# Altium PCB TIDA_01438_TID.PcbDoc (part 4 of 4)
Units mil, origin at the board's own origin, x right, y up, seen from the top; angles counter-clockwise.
Board outline 6250 x 2150 mil, 4 copper layers (Top Layer, V-, V+, Bottom Layer), stack 61.6 mil thick; 360 components, 217 nets, 1141 pads, 401 vias.
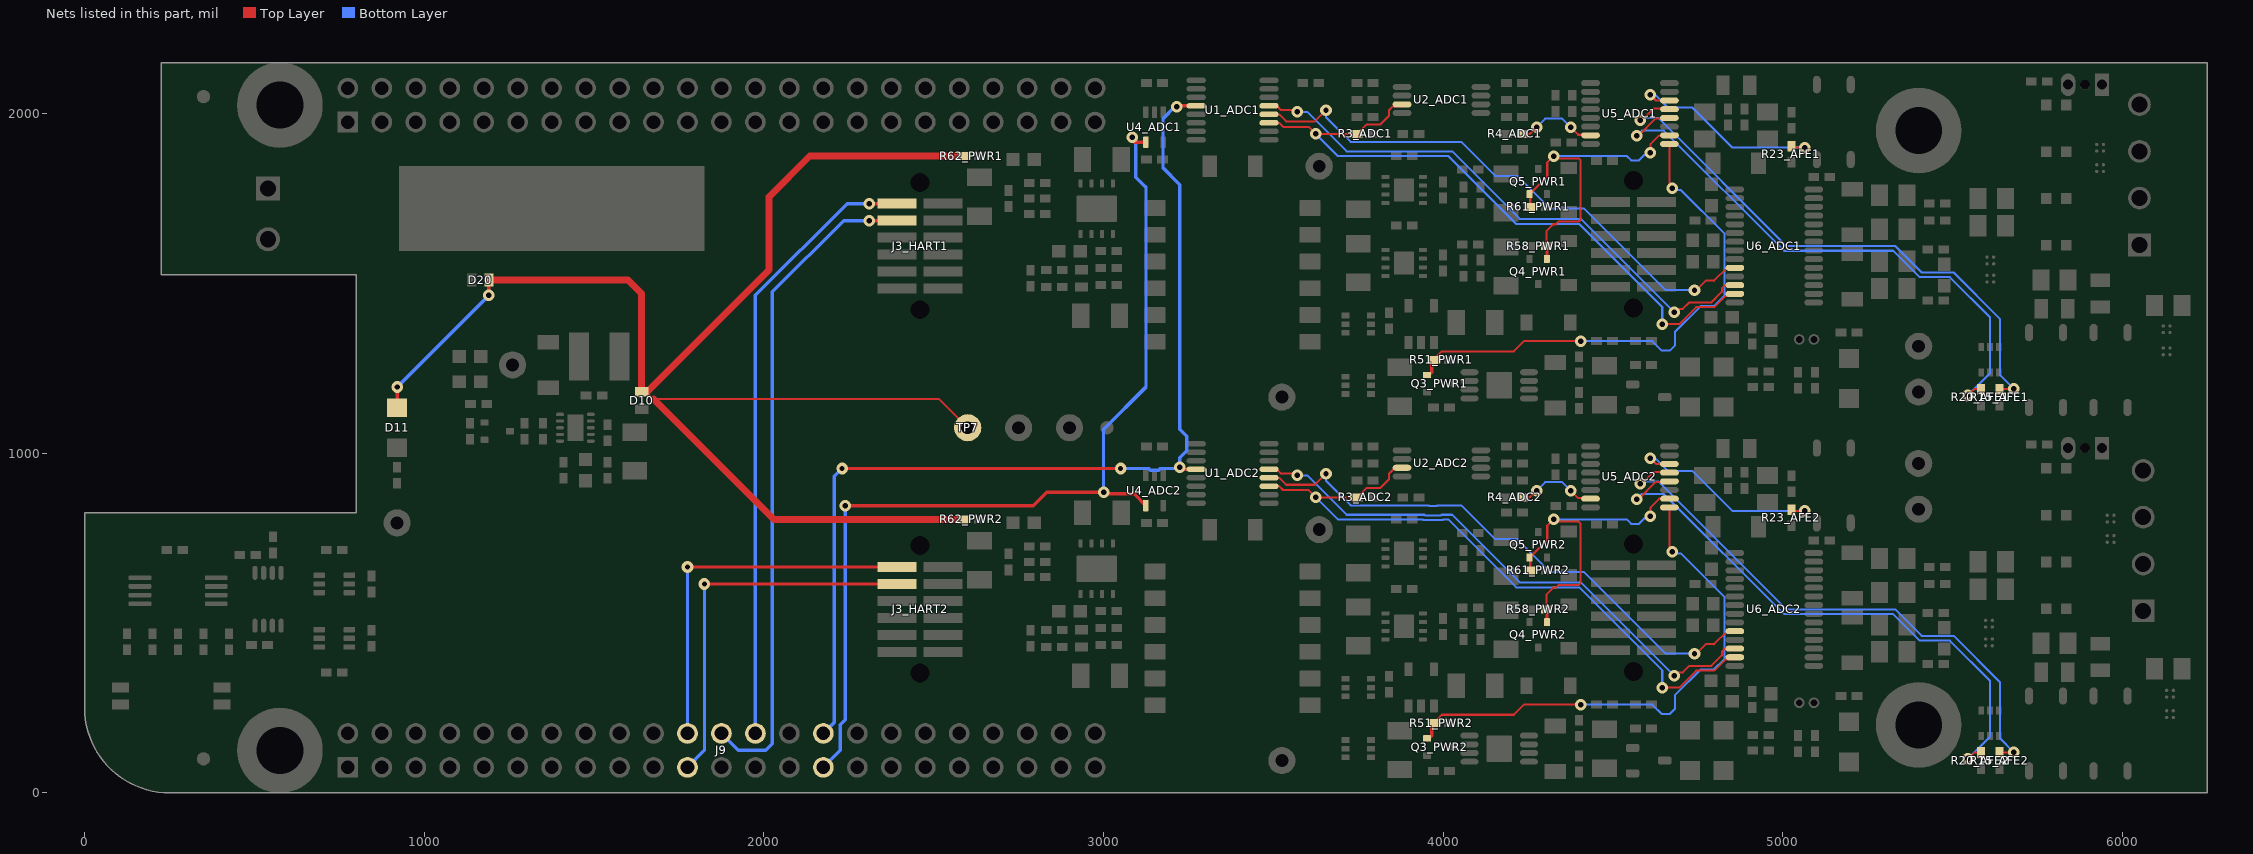
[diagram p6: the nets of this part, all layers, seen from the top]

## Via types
v1: diameter 34, hole 16, Top Layer to Bottom Layer, 337 vias
v2: diameter 19.68, hole 7.87, Top Layer to Bottom Layer, 36 vias
v3: diameter 39.37, hole 19.68, Top Layer to Bottom Layer, 24 vias
v4: diameter 30, hole 10, Top Layer to Bottom Layer, 4 vias

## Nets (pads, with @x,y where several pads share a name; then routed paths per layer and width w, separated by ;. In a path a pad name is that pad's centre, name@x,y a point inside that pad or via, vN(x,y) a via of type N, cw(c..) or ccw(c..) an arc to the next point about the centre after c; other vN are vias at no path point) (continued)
SPI_ISO_CS_ADC1: U1_ADC1.12 U6_ADC1.10 | length 1663.9
  Top Layer w6: v1@3650,2010 v1@3655,2015 ; v1(3655,2010) 3622.13,1977.13 3537.87,1977.13 3518.31,1996.69 U1_ADC1.12@3488.41,1996.69 ; v1(4740,1480) 4745.58,1480 4773.45,1507.87 4796.55,1507.87 4797.11,1507.31 4835.82,1546.02 U6_ADC1.10@4858.86,1546.02 U6_ADC1.10@4858.86,1544.76 ; U1_ADC1.12@3488.41,1996.69 3487.28,1996.69 U1_ADC1.12@3487.28,1997.82 U1_ADC1.12@3488.41,1996.69
  Bottom Layer w6: v1(3655,2010) 3655,1989.24 3727.62,1916.62 4053,1916.62 4152.87,1816.75 4218.62,1816.75 4315.37,1720 4415,1720 4655,1480 v1(4740,1480)
SPI_ISO_CS_ADC2: U1_ADC2.12 U6_ADC2.10 | length 1661.5
  Top Layer w6: U1_ADC2.12@3488.41,926.69 3518.31,926.69 3537.87,907.13 3622.13,907.13 v1(3655,940) ; v1@3650,940 v1@3655,945 ; v1(4740,410) 4745.58,410 4773.45,437.87 4796.55,437.87 4797.11,437.31 4835.82,476.02 U6_ADC2.10@4858.86,476.02 U6_ADC2.10@4858.86,474.76
  Bottom Layer w6: v1(3655,940) 3655,919.24 3727.62,846.62 3956.7,846.62 3958.45,844.87 3981.55,844.87 3983.3,846.62 4053,846.62 4152.87,746.75 4218.62,746.75 4315.37,650 4415,650 4655,410 v1(4740,410)
SPI_ISO_MISO_ADC1: R3_ADC1.2 U1_ADC1.11 U2_ADC1.7 U6_ADC1.13 | length 2007.5
  Top Layer w6: U1_ADC1.11@3487.28,1972.82 3517.19,1972.82 3528.31,1961.69 3528.69,1961.69 3529.25,1961.13 3603.87,1961.13 v1(3625,1940) R3_ADC1.2@3746.38,1940 3773.69,1967.32 3813.87,1967.32 3840.43,1993.87 3840.43,2009.79 3851.98,2021.35 3873,2021.35 U2_ADC1.7@3878.86,2027.2 ; v1(4645,1380) 4695,1380 4745,1430 4798.59,1430 4831.98,1463.39 4853,1463.39 U6_ADC1.13@4858.86,1469.25 U6_ADC1.13@4834.25,1469.25
  Bottom Layer w6: v1(3625,1940) 3690,1875 4015,1875 4215,1675 4400.38,1675 4645,1430.38 v1(4645,1380)
SPI_ISO_MISO_ADC2: R3_ADC2.2 U1_ADC2.11 U2_ADC2.7 U6_ADC2.13 | length 2008
  Top Layer w6: U1_ADC2.11@3487.28,902.82 3517.19,902.82 3528.31,891.69 3528.69,891.69 3529.25,891.13 3603.87,891.13 v1(3625,870) R3_ADC2.2@3746.38,870 3773.69,897.32 3813.87,897.32 3840.43,923.87 3840.43,939.79 3855.59,954.95 U2_ADC2.7@3878.86,954.95 ; v1(4645,310) 4695,310 4745,360 4798.59,360 4831.98,393.39 4853,393.39 U6_ADC2.13@4858.86,399.25 U6_ADC2.13@4834.25,399.25
  Bottom Layer w6: v1(3625,870) 3690,805 3939.46,805 3941.21,803.25 3998.79,803.25 4000.54,805 4015,805 4215,605 4400.38,605 4645,360.38 v1(4645,310)
SPI_ISO_MOSI_ADC1: U1_ADC1.13 U6_ADC1.12 | length 1670.9
  Top Layer w6: U1_ADC1.13@3487.28,2022.82 3509.47,2022.82 3521.71,2010.57 3559.43,2010.57 3565,2005 v1(3570,2005) ; v1(4680,1415) 4685,1415 4695,1425 4705.96,1425 4724.83,1443.87 4789.25,1443.87 4820.43,1475.05 4820.43,1485.43 4830,1495 4830.16,1494.84 U6_ADC1.12@4858.86,1494.84 U6_ADC1.12@4853,1488.98
  Bottom Layer w6: v1(3570,2005) 3600,2005 3716.13,1888.87 4026.13,1888.87 4225,1690 4405,1690 v1(4680,1415)
SPI_ISO_MOSI_ADC2: U1_ADC2.13 U6_ADC2.12 | length 1672.4
  Top Layer w6: U1_ADC2.13@3487.28,952.82 3509.47,952.82 3521.71,940.57 3559.43,940.57 3565,935 v1(3570,935) ; v1(4680,345) 4685,345 4695,355 4705.96,355 4724.83,373.87 4789.25,373.87 4820.43,405.05 4820.43,415.43 4830,425 4830.16,424.84 U6_ADC2.12@4858.86,424.84 U6_ADC2.12@4853,418.98
  Bottom Layer w6: v1(3570,935) 3600,935 3716.13,818.87 3945.21,818.87 3946.96,817.12 3993.04,817.12 3994.79,818.87 4026.13,818.87 4225,620 4405,620 v1(4680,345)
SPI_MISO: J9.29 U4_ADC1.4 U4_ADC2.4 | length 2893.9
  Top Layer w10: v1@2225.71,845.71 2793.36,845.71 2832.65,885 v1(3000,885) 3004.87,880.13 3089.99,880.13 U4_ADC2.4@3124.41,845.71 ; v1(3085,1930) 3085,1921.42 3090.71,1915.71 U4_ADC1.4@3124.41,1915.71
  Bottom Layer w10: J9.29@2175,75 2225,125 2225,200 2240,215 v1(2240,845.71) ; v1(3000,885) 3000,1070 3125,1195 3125,1785 3122.75,1785 3095.13,1812.63 3095.13,1919.87 v1(3085,1930)
SPI_MOSI: J9.30 U1_ADC1.4 U1_ADC2.4 | length 3038.3
  Top Layer w10: v1(2230,955) v1(3050,955) ; v1(3215,2020) 3210,2020 3212.82,2022.82 U1_ADC1.4@3272.72,2022.82 ; v1(3224.14,959.14) 3224.14,955.86 3227.18,952.82 U1_ADC2.4@3272.72,952.82
  Bottom Layer w10: J9.30@2175,175 2207.13,207.13 2207.13,932.13 v1(2230,955) ; v1(3050,955) 3132.75,955 3137.63,950.13 3162.37,950.13 3167.25,955 3215,955 3220,960 3220.86,959.14 v1(3224.14,959.14) 3224.14,986.89 3244.87,1007.63 3244.87,1049.87 3224.14,1070.61 3224.14,1790.86 3175,1840 3175,1985 v1@3210,2020
SW_4_20MA_ADC1: Q3_PWR1.1 R51_PWR1.2 U5_ADC1.1 | length 1557
  Top Layer w6: R51_PWR1.2@3971.38,1275 3996.38,1300 4207.75,1300 4237.75,1330 v1(4405,1330) ; U5_ADC1.1@4666.14,1910.43 4666.14,1788.86 v1(4675,1780)
  Top Layer w10: Q3_PWR1.1@3958.5,1230.59 3966.38,1238.46 R51_PWR1.2@3966.38,1275
  Bottom Layer w6: v1(4405,1330) 4615.58,1330 4643.45,1302.13 4666.55,1302.13 4682.87,1318.45 4682.87,1358.25 4757.87,1433.25 4797.29,1433.25 4827.87,1463.83 4827.87,1647.13 4700,1775 4675,1775 v1(4675,1780)
SW_4_20MA_ADC2: Q3_PWR2.1 R51_PWR2.2 U5_ADC2.1 | length 1557
  Top Layer w6: R51_PWR2.2@3971.38,205 3996.38,230 4207.75,230 4237.75,260 v1(4405,260) ; U5_ADC2.1@4666.14,840.43 4666.14,718.86 v1(4675,710)
  Top Layer w10: Q3_PWR2.1@3958.5,160.59 3966.38,168.46 R51_PWR2.2@3966.38,205
  Bottom Layer w6: v1(4405,260) 4615.58,260 4643.45,232.13 4666.55,232.13 4682.87,248.45 4682.87,288.25 4757.87,363.25 4797.29,363.25 4827.87,393.83 4827.87,577.13 4700,705 4675,705 v1(4675,710)
SW_ASUPPLY_PWR1: Q4_PWR1.1 Q5_PWR1.1 R58_PWR1.1 R61_PWR1.1 U5_ADC1.2 | length 1032.2
  Top Layer w6: R61_PWR1.1@4256.38,1725 4256.38,1766.54 4254.41,1768.5 4259.95,1768.5 4306.44,1815 4306.44,1856.44 4318.35,1868.35 4398.52,1868.35 4404.89,1861.98 4404.89,1688.02 4398.52,1681.65 4339.2,1681.65 4331.68,1674.13 4324.13,1674.13 4303.62,1653.62 R58_PWR1.1@4303.62,1610 ; v1(4610,1885) 4610,1910 4636.02,1936.02 U5_ADC1.2@4666.14,1936.02
  Top Layer w10: R58_PWR1.1@4303.62,1610 4305.59,1608.03 Q4_PWR1.1@4305.59,1566.5
  Bottom Layer w6: v1(4325,1875) 4540.58,1875 4553.45,1862.13 4576.55,1862.13 4592.73,1878.32 4603.32,1878.32 v1(4610,1885)
SW_ASUPPLY_PWR2: Q4_PWR2.1 Q5_PWR2.1 R58_PWR2.1 R61_PWR2.1 U5_ADC2.2 | length 1032.2
  Top Layer w6: R61_PWR2.1@4256.38,655 4256.38,696.54 4254.41,698.5 4259.95,698.5 4306.44,745 4306.44,786.44 4318.35,798.35 4398.52,798.35 4404.89,791.98 4404.89,618.02 4398.52,611.65 4339.2,611.65 4331.68,604.13 4324.13,604.13 4303.62,583.62 R58_PWR2.1@4303.62,540 ; v1(4610,815) 4610,840 4636.02,866.02 U5_ADC2.2@4666.14,866.02
  Top Layer w10: R58_PWR2.1@4303.62,540 4305.59,538.03 Q4_PWR2.1@4305.59,496.5
  Bottom Layer w6: v1(4325,805) 4540.58,805 4553.45,792.13 4576.55,792.13 4592.73,808.32 4603.32,808.32 v1(4610,815)
SW_BURDEN_ADC1: R23_AFE1.1 U5_ADC1.6 | length 623.7
  Top Layer w6: v1(4610,2055) 4626.61,2038.39 U5_ADC1.6@4666.14,2038.39 ; R23_AFE1.1@5025,1903.62 5028.62,1900 v1(5065,1900)
  Bottom Layer w6: v1(4610,2055) 4624.62,2055 4661.75,2017.87 4733.35,2017.87 4851.22,1900 5060,1900 v1(5065,1900)
SW_BURDEN_ADC2: R23_AFE2.1 U5_ADC2.6 | length 623.7
  Top Layer w6: v1(4610,985) 4626.61,968.39 U5_ADC2.6@4666.14,968.39 ; R23_AFE2.1@5025,833.62 5028.62,830 v1(5065,830)
  Bottom Layer w6: v1(4610,985) 4624.62,985 4661.75,947.87 4733.35,947.87 4851.22,830 5060,830 v1(5065,830)
SW_HV_ADC1: R20_AFE1.1 U5_ADC1.4 | length 1693.5
  Top Layer w6: v1(4570,1935) 4575,1935 4625,1985 4661.63,1985 U5_ADC1.4@4660.28,1986.35 ; v1(5545,1170) 5563.62,1188.62 R20_AFE1.1@5583.35,1188.62
  Bottom Layer w6: v1@4572.21,1935 v1(4570,1935) 4585,1950 4650,1950 5003.87,1596.13 5324.83,1596.13 5402.71,1518.25 5491.75,1518.25 5610,1400 5610,1235 v1(5545,1170)
SW_HV_ADC2: R20_AFE2.1 U5_ADC2.4 | length 1693.5
  Top Layer w6: v1(4570,865) 4575,865 4625,915 4661.63,915 U5_ADC2.4@4660.28,916.35 ; v1(5545,100) 5563.62,118.62 R20_AFE2.1@5583.35,118.62
  Bottom Layer w6: v1@4572.21,865 v1(4570,865) 4585,880 4650,880 5003.87,526.13 5324.83,526.13 5402.71,448.25 5491.75,448.25 5610,330 5610,165 v1(5545,100)
SW_RTD_LOOP_ADC1: R15_AFE1.1 U5_ADC1.5 | length 1685.5
  Top Layer w6: v1(4580,1980) 4580,1985 4585,1980 4620,2015 4663.35,2015 U5_ADC1.5@4666.14,2017.8 ; R15_AFE1.1@5638.35,1188.62 5678.62,1188.62 v1(5680,1190)
  Bottom Layer w6: v1@4590,1980 4582.75,1987.25 4632.75,1987.25 5010,1610 5330.58,1610 5408.45,1532.13 5502.87,1532.13 5640,1395 5640,1230 v1(5680,1190)
SW_RTD_LOOP_ADC2: R15_AFE2.1 U5_ADC2.5 | length 1685.5
  Top Layer w6: v1(4580,910) 4580,915 4585,910 4620,945 4663.35,945 U5_ADC2.5@4666.14,947.8 ; R15_AFE2.1@5638.35,118.62 5678.62,118.62 v1(5680,120)
  Bottom Layer w6: v1@4590,910 4582.75,917.25 4632.75,917.25 5010,540 5330.58,540 5408.45,462.13 5502.87,462.13 5640,325 5640,160 v1(5680,120)
SW_TEMP_ADC1: R4_ADC1.2 U5_ADC1.15 | length 240.1
  Top Layer w6: R4_ADC1.2@4233.62,1940 4255,1940 v1(4275,1960) ; v1(4375,1960) 4397.31,1937.68 4433.86,1937.68 U5_ADC1.15@4433.86,1936.02
  Bottom Layer w6: v1(4275,1960) 4300,1985 4350,1985 v1(4375,1960)
SW_TEMP_ADC2: R4_ADC2.2 U5_ADC2.15 | length 240.1
  Top Layer w6: R4_ADC2.2@4233.62,870 4255,870 v1(4275,890) ; v1(4375,890) 4397.31,867.68 4433.86,867.68 U5_ADC2.15@4433.86,866.02
  Bottom Layer w6: v1(4275,890) 4300,915 4350,915 v1(4375,890)
UART_RXD1: J3_HART1.1 J9.26 | length 1819.3
  Top Layer w10: v1(2310,1735) J3_HART1.1@2392.48,1735
  Bottom Layer w10: J9.26@1975,175 1975,1465 2245,1735 v1(2310,1735)
UART_RXD2: J3_HART2.1 J9.22 | length 1107.5
  Top Layer w10: v1(1775,665) J3_HART2.1@2392.48,665
  Bottom Layer w10: J9.22@1775,175 v1(1775,665)
UART_TXD1: J3_HART1.3 J9.24 | length 1963.5
  Top Layer w10: v1(2310,1685) J3_HART1.3@2392.48,1685
  Bottom Layer w10: J9.24@1875,175 1925,125 2005,125 2025,145 2025,1475 2235,1685 v1(2310,1685)
UART_TXD2: J3_HART2.3 J9.21 | length 1128.2
  Top Layer w10: v1(1825,615) J3_HART2.3@2392.48,615
  Bottom Layer w10: J9.21@1775,75 1825,125 v1(1825,615)
VIN: D10.1 D11.2 D20.1 R62_PWR1.1 R62_PWR2.1 TP7.1 | length 4654.6
  Top Layer w6: D10.1@1654.13,1180.59 1674.72,1160 2515,1160 TP7.1@2600,1075
  Top Layer w10: D11.2@920,1134.06 v1(920,1195) ; v1(1190,1465) 1190,1509.41 D20.1@1190.59,1510
  Top Layer w20: D20.1@1190.59,1510 1600,1510 1640,1470 D10.1@1640,1180.59 1654.13,1180.59 1655.59,1180.59 2015,1540 2015,1755 2135,1875 R62_PWR1.1@2586.38,1875 ; 1674.72,1160 2029.72,805 R62_PWR2.1@2586.38,805
  Bottom Layer w10: v1(920,1195) 1185,1460 1190,1460 v1(1190,1465)
pads on no net: D4_AFE1.2 D4_AFE1.5 D4_AFE2.2 D4_AFE2.5 D13_PWR1.2 D13_PWR1.5 D13_PWR2.2 D13_PWR2.5 D16_PWR1.2 D16_PWR1.5 D16_PWR2.2 D16_PWR2.5 FID1.1 FID2.1 FID3.1 J3_HART1.2 J3_HART1.4 J3_HART1.6 J3_HART1.8 J3_HART1.10 J3_HART1.12 J3_HART1.MH1 J3_HART1.MH2 J3_HART2.2 J3_HART2.4 J3_HART2.6 J3_HART2.8 J3_HART2.10 J3_HART2.12 J3_HART2.MH1 J3_HART2.MH2 J4_HART1.2 J4_HART1.5 J4_HART1.6 J4_HART1.10 J4_HART1.11 J4_HART1.12 J4_HART1.MH1 J4_HART1.MH2 J4_HART2.2 J4_HART2.5 J4_HART2.6 J4_HART2.10 J4_HART2.11 J4_HART2.12 J4_HART2.MH1 J4_HART2.MH2 J8.3 J8.4 J8.5 J8.6 J8.7 J8.8 J8.9 J8.10 J8.13 J8.14 J8.15 J8.16 J8.17 J8.18 J8.19 J8.20 J8.21 J8.22 J8.23 J8.24 J8.25 J8.26 J8.27 J8.28 J8.29 J8.30 J8.31 J8.32 J8.33 J8.34 J8.35 J8.36 J8.37 J8.38 J8.39 J8.40 J8.41 J8.42 J8.43 J8.44 J8.45 J8.46 J9.9 J9.10 J9.11 J9.12 J9.13 J9.14 J9.15 J9.16 J9.17 J9.18 J9.23 J9.32 J9.33 J9.34 J9.35 J9.36 J9.37 J9.38 J9.39 J9.40 J9.41 Logo1.0 MH1.1 MH2.1 MH3.1 MH4.1 T1_PWR1.1 T1_PWR1.3 T1_PWR1.5 T1_PWR1.6 T1_PWR2.1 T1_PWR2.3 T1_PWR2.5 T1_PWR2.6 U3_ADC1.MH U3_ADC2.MH U5_ADC1.9 U5_ADC2.9 U6_ADC1.14 U6_ADC2.14 U12_PWR1.3 U12_PWR1.6 U12_PWR1.7 U12_PWR2.3 U12_PWR2.6 U12_PWR2.7 U13_PWR1.4 U13_PWR1.5 U13_PWR2.4 U13_PWR2.5 U14_PWR1.3 U14_PWR1.7 U14_PWR2.3 U14_PWR2.7 U16_PWR1.3 U16_PWR1.7 U16_PWR2.3 U16_PWR2.7
copper on no net: | length 104231.7
  Top Layer w1: 9194.12,4730.32 9293.8,4830 9413.8,4950 9533.8,5070 9653.8,5190 9773.8,5310 9893.8,5430 10013.8,5550 10133.8,5670 10253.8,5790 10313.8,5850 ; 9194.12,4790.32 9233.8,4830 9353.8,4950 9473.8,5070 9593.8,5190 9713.8,5310 9833.8,5430 9953.8,5550 10073.8,5670 10193.8,5790 10313.8,5910 ; 9194.12,4850.32 9293.8,4950 9413.8,5070 9533.8,5190 9653.8,5310 9773.8,5430 9893.8,5550 10013.8,5670 10133.8,5790 10253.8,5910 10313.8,5970 ; 9194.12,4910.32 9233.8,4950 9353.8,5070 9473.8,5190 9593.8,5310 9713.8,5430 9833.8,5550 9953.8,5670 10073.8,5790 10193.8,5910 10313.8,6030 ; 9194.12,4970.32 9293.8,5070 9413.8,5190 9533.8,5310 9653.8,5430 9773.8,5550 9893.8,5670 10013.8,5790 10133.8,5910 10253.8,6030 ; 9194.12,5030.32 9233.8,5070 9353.8,5190 9473.8,5310 9593.8,5430 9713.8,5550 9833.8,5670 9953.8,5790 10073.8,5910 10193.8,6030 ; 9194.12,5090.32 9293.8,5190 9413.8,5310 9533.8,5430 9653.8,5550 9773.8,5670 9893.8,5790 10013.8,5910 10133.8,6030 ; 9194.12,5150.32 9233.8,5190 9353.8,5310 9473.8,5430 9593.8,5550 9713.8,5670 9833.8,5790 9953.8,5910 10073.8,6030 ; 9194.12,5210.32 9293.8,5310 9413.8,5430 9533.8,5550 9653.8,5670 9773.8,5790 9893.8,5910 10013.8,6030 ; 9194.12,5270.32 9233.8,5310 9353.8,5430 9473.8,5550 9593.8,5670 9713.8,5790 9833.8,5910 9953.8,6030 ; 9194.12,5330.32 9293.8,5430 9413.8,5550 9533.8,5670 9653.8,5790 9773.8,5910 9893.8,6030 ; 9194.12,5390.32 9233.8,5430 9353.8,5550 9473.8,5670 9593.8,5790 9713.8,5910 9833.8,6030 ; 9194.12,5450.32 9293.8,5550 9413.8,5670 9533.8,5790 9653.8,5910 9773.8,6030 ; 9194.12,5510.32 9233.8,5550 9353.8,5670 9473.8,5790 9593.8,5910 9713.8,6030 ; 9194.12,5570.32 9293.8,5670 9413.8,5790 9533.8,5910 9653.8,6030 ; 9194.12,5630.32 9233.8,5670 9353.8,5790 9473.8,5910 9593.8,6030 ; 9194.12,5690.32 9293.8,5790 9413.8,5910 9533.8,6030 ; 9194.12,5750.32 9233.8,5790 9353.8,5910 9473.8,6030 ; 9194.12,5810.32 9293.8,5910 9413.8,6030 ; 9194.12,5870.32 9233.8,5910 9353.8,6030 ; 9194.12,5930.32 9293.8,6030 ; 9194.12,5990.32 9233.8,6030 ; 9233.8,4710 9353.8,4830 9473.8,4950 9593.8,5070 9713.8,5190 9833.8,5310 9953.8,5430 10073.8,5550 10193.8,5670 10313.8,5790 ; 9293.8,4710 9413.8,4830 9533.8,4950 9653.8,5070 9773.8,5190 9893.8,5310 10013.8,5430 10133.8,5550 10253.8,5670 10313.8,5730 ; 9353.8,4710 9473.8,4830 9593.8,4950 9713.8,5070 9833.8,5190 9953.8,5310 10073.8,5430 10193.8,5550 10313.8,5670 ; 9413.8,4710 9533.8,4830 9653.8,4950 9773.8,5070 9893.8,5190 10013.8,5310 10133.8,5430 10253.8,5550 10313.8,5610 ; 9473.8,4710 9593.8,4830 9713.8,4950 9833.8,5070 9953.8,5190 10073.8,5310 10193.8,5430 10313.8,5550 ; 9533.8,4710 9653.8,4830 9773.8,4950 9893.8,5070 10013.8,5190 10133.8,5310 10253.8,5430 10313.8,5490 ; 9593.8,4710 9713.8,4830 9833.8,4950 9953.8,5070 10073.8,5190 10193.8,5310 10313.8,5430 ; 9653.8,4710 9773.8,4830 9893.8,4950 10013.8,5070 10133.8,5190 10253.8,5310 10313.8,5370 ; 9713.8,4710 9833.8,4830 9953.8,4950 10073.8,5070 10193.8,5190 10313.8,5310 ; 9773.8,4710 9893.8,4830 10013.8,4950 10133.8,5070 10253.8,5190 10313.8,5250 ; 9833.8,4710 9953.8,4830 10073.8,4950 10193.8,5070 10313.8,5190 ; 9893.8,4710 10013.8,4830 10133.8,4950 10253.8,5070 10313.8,5130 ; 9953.8,4710 10073.8,4830 10193.8,4950 10313.8,5070 ; 10013.8,4710 10133.8,4830 10253.8,4950 10313.8,5010 ; 10073.8,4710 10193.8,4830 10313.8,4950 ; 10133.8,4710 10253.8,4830 10313.8,4890 ; 10193.8,4710 10313.8,4830 ; 10253.8,4710 10313.8,4770
  Top Layer w10: 225.01,1530.01 ccw(c230.01,1530.01) 230.01,1525.01 cw(c230.01,1530.01) 225.01,1530.01 ; 225.01,2155.01 cw(c230.01,2155.01) 230.01,2160.02 ccw(c230.01,2155.01) 225.01,2155.01
  Top Layer w15: 5775,4830 6184.91,4830 7114.66,4830 7974.42,4830 8624.26,4830 9194.12,4830 10313.8,4830 ; 5775,4950 6184.91,4950 7114.66,4950 7974.42,4950 8624.26,4950 9194.12,4950 10313.8,4950 ; 5775,5070 6184.91,5070 7114.66,5070 7974.42,5070 8624.26,5070 9194.12,5070 10313.8,5070 ; 5775,5190 6184.91,5190 7114.66,5190 7974.42,5190 8624.26,5190 9194.12,5190 10313.8,5190 ; 5775,5310 6184.91,5310 7114.66,5310 7974.42,5310 8624.26,5310 9194.12,5310 10313.8,5310 ; 5775,5430 6184.91,5430 7114.66,5430 7974.42,5430 8624.26,5430 9194.12,5430 10313.8,5430 ; 5775,5550 6184.91,5550 7114.66,5550 7974.42,5550 8624.26,5550 9194.12,5550 10313.8,5550 ; 5775,5670 6184.91,5670 7114.66,5670 7974.42,5670 8624.26,5670 9194.12,5670 10313.8,5670 ; 5775,5790 6184.91,5790 7114.66,5790 7974.42,5790 8624.26,5790 9194.12,5790 10313.8,5790 ; 5775,5910 6184.91,5910 7114.66,5910 7974.42,5910 8624.26,5910 9194.12,5910 10313.8,5910 ; 5775,6030 10313.8,6030 ; 6184.91,6150 6184.91,4710 ; 7114.66,6150 7114.66,4710 ; 7974.42,6150 7974.42,4710 ; 8624.26,6150 8624.26,4710 ; 9194.12,6150 9194.12,4710 ; 6184.91,4710 5775,4710 5775,6150 10313.8,6150 10313.8,4710 9194.12,4710 ; 6184.91,4710 7114.66,4710 ; 7114.66,4710 7974.42,4710 ; 7974.42,4710 8624.26,4710 ; 8624.26,4710 9194.12,4710
  Top Layer w20: v1(5565,1005) 5622.52,1005 5640,987.52 ; v1(5565,2075) 5622.52,2075 5640,2057.52 ; v1(6075,105) 6132.52,105 ; v1(6075,1175) 6132.52,1175
  other v3: 575,27.56 490.61,76.28 659.39,76.28 5400,102.56 5315.61,151.28 5484.39,151.28 490.61,173.72 659.39,173.72 575,222.44 5315.61,248.72 5484.39,248.72 5400,297.44 5400,1852.56 5315.61,1901.28 5484.39,1901.28 575,1927.56 490.61,1976.28 659.39,1976.28 5315.61,1998.72 5484.39,1998.72 5400,2047.44 490.61,2073.72 659.39,2073.72 575,2122.44

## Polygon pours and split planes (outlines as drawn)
DVDD on V+ "DVDD" (solid, remove dead copper, pour order 37): 3300,2150 3300,0 0,0 0,2150 3300,2150
DVDD_ISO_ADC1 on V+ "DVDD_CH1" (solid, remove dead copper, pour order 32): 3460,2150 3460,1100 6250,1100 6250,2150
DVDD_ISO_ADC2 on V+ "DVDD_CH2" (solid, remove dead copper, pour order 33): 3460,1050 3460,0 6250,0 6250,1050
DGND on V- "GND" (solid, remove dead copper, pour order 36): 3300,2150 3300,0 0,0 0,2150 3300,2150
GND_ADC1 on V- "GND_CH1" (solid, remove dead copper, pour order 34): 3460,1100 3460,2150 6250,2150 6250,1100
GND_ADC2 on V- "GND_CH2" (solid, remove dead copper, pour order 35): 3460,0 3460,1050 6250,1050 6250,0
NetC27_AFE1_1 on Bottom Layer "LOCALTEMP_CH1_N" (solid, remove dead copper, pour order 29): 5600,2025 6250,2025 6250,1830 5600,1830
NetC23_AFE1_1 on Bottom Layer "LOCALTEMP_CH1_P" (solid, remove dead copper, pour order 31): 5600,1820 6250,1820 6250,1625 5600,1625
NetC27_AFE2_1 on Bottom Layer "LOCALTEMP_CH2_N" (solid, remove dead copper, pour order 28): 5600,950 6250,950 6250,755 5600,755
NetC23_AFE2_1 on Bottom Layer "LOCALTEMP_CH2_P" (solid, remove dead copper, pour order 30): 5600,745 6250,745 6250,550 5600,550
GND_ADC1 on Top Layer "GND_ADC1_L01_P059" (solid, remove dead copper, pour order 59): 5885,1989 6043,2089 6073,2081 6122.67,2067.76 6102,2006 5985,1904 5885,1904
NetD101_AFE1_A1 on Top Layer "NETD101_AFE1_A1_L01_P057" (solid, pour order 57): 5907.85,1847 5961,1847 5961,1893.22 5907.85,1893.22
NetD7_AFE2_A1 on Top Layer "NETD7_AFE2_A1_L01_P051" (solid, pour order 51): 5580.45,447.41 5633.6,447.41 5633.6,493.63 5580.45,493.63
GND_ADC1 on Top Layer "GND_ADC1_L01_P049" (solid, remove dead copper, pour order 49): 6084,1295 6184,1295 6184,1210 6084,1210
NetD5_AFE1_A1 on Top Layer "NETD5_AFE1_A1_L01_P047" (solid, pour order 47): 6103.43,1306.23 6156.57,1306.23 6156.57,1356.39 6103.42,1356.39
NetD101_AFE2_A1 on Top Layer "NETD101_AFE2_A1_L01_P045" (solid, pour order 45): 5931.54,752.4 5984.69,752.4 5984.69,802.55 5931.54,802.55
GND_ADC2 on Top Layer "GND_ADC2_L01_P043" (solid, pour order 43): 5913,897 6034,983.43 6072,1013 6105.41,950 5996.5,813.5 5913,812
NetD5_AFE2_A1 on Top Layer "NETD5_AFE2_A1_L01_P041" (solid, pour order 41): 6113.35,238.78 6166.5,238.78 6166.5,285 6113.35,285
GND_ADC2 on Top Layer "GND_ADC2_L01_P039" (solid, remove dead copper, pour order 39): 6090,225 6190,225 6190,140 6090,140
NetD7_AFE1_A1 on Top Layer "NETD7_AFE1_A1_L01_P053" (solid, pour order 53): 5584,1518.92 5637.15,1518.92 5637.15,1565.77 5584,1565.77
GND_ADC1 on Top Layer "GND_ADC1_L01_P055" (solid, remove dead copper, pour order 55): 5570,1511 5654,1511 5726,1550 5756.69,1538.54 5765.55,1481.48 5756.69,1481.48 5726,1470 5666,1465 5570,1465

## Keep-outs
Keep-Out Layer:
  lines w10: 800,825 800,1525 225,1525 225,2150 6250,2150 6250,0 250,0 cw(c250,250) 0,250 0,825 800,825 ; 800,825 800,825
  text ".Layer_Name" at 577,-858.49 h60

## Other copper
Top Layer:
  text "Layer" at 5835,6060 h60
  text "Name" at 6244.91,6060 h60
  text "Material" at 7174.66,6060 h60
  text "Thickness" at 8034.42,6060 h60
  text "Constant" at 8684.26,6060 h60
  text "Board Layer Stack" at 9254.12,6060 h60
  text "1" at 5835,5940 h60
  text "Top Overlay" at 6244.91,5940 h60
  text "2" at 5835,5820 h60
  text "Top Solder" at 6244.91,5820 h60
  text "Solder Resist" at 7174.66,5820 h60
  text "0.40mil" at 8034.42,5820 h60
  text "3.5" at 8684.26,5820 h60
  text "3" at 5835,5700 h60
  text "Top Layer" at 6244.91,5700 h60
  text "Copper" at 7174.66,5700 h60
  text "1.40mil" at 8034.42,5700 h60
  text "4" at 5835,5580 h60
  text "Dielectric 1" at 6244.91,5580 h60
  text "8.00mil" at 8034.42,5580 h60
  text "4.2" at 8684.26,5580 h60
  text "5" at 5835,5460 h60
  text "V-" at 6244.91,5460 h60
  text "Copper" at 7174.66,5460 h60
  text "1.40mil" at 8034.42,5460 h60
  text "6" at 5835,5340 h60
  text "Dielectric 2" at 6244.91,5340 h60
  text "FR-4" at 7174.66,5340 h60
  text "40.00mil" at 8034.42,5340 h60
  text "4.2" at 8684.26,5340 h60
  text "7" at 5835,5220 h60
  text "V+" at 6244.91,5220 h60
  text "Copper" at 7174.66,5220 h60
  text "1.40mil" at 8034.42,5220 h60
  text "8" at 5835,5100 h60
  text "Dielectric 3" at 6244.91,5100 h60
  text "8.00mil" at 8034.42,5100 h60
  text "4.2" at 8684.26,5100 h60
  text "9" at 5835,4980 h60
  text "Bottom Layer" at 6244.91,4980 h60
  text "Copper" at 7174.66,4980 h60
  text "1.40mil" at 8034.42,4980 h60
  text "10" at 5835,4860 h60
  text "Bottom Solder" at 6244.91,4860 h60
  text "Solder Resist" at 7174.66,4860 h60
  text "0.40mil" at 8034.42,4860 h60
  text "3.5" at 8684.26,4860 h60
  text "11" at 5835,4740 h60
  text "Bottom Overlay" at 6244.91,4740 h60
  text "16..33V" at 265,1900 h30
  text "+" at 610,1810 h40
  text "CH1" at 2140,1770 h60
  text "-" at 610,1575 h40
  text "TIDA-01438E1" at 1830,1050 h60
  text "CH2" at 2140,700 h60
  text ".Layer_Name" at 577,-858.49 h60
Bottom Layer:
  text ".Layer_Name" at 577,-858.49 h60

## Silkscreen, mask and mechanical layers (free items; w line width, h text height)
Top Overlay:
  lines w10: 3380.02,105.02 3380.02,2055.02
  text "CAPE-ID AND" at 1005.02,280.02 h40 r90
  text "ADDR-DEC" at 1080.02,280.02 h40 r90
  text ".Layer_Name" at 577,-858.49 h60
Bottom Overlay:
  text ".Layer_Name" at 577,-858.49 h60
Top Paste:
  text ".Layer_Name" at 577,-858.49 h60
Bottom Paste:
  text ".Layer_Name" at 577,-858.49 h60
Top Solder:
  rectangle: 1700,1035 2389.78,1114.98
  text ".Layer_Name" at 577,-858.49 h60
  text ".Layer_Name" at 577,-858.49 h60
Bottom Solder:
  rectangle: 5600.29,1625 6219.74,2025
  rectangle: 5600.29,550 6219.74,949.39
  text ".Layer_Name" at 577,-858.49 h60
Drill Guide:
  text ".Layer_Name" at 577,-858.49 h60
M1 Board Outline:
  the board outline again, w10
  text ".Layer_Name" at 577,-858.49 h60
M2 Board Dimensions:
  lines w10: 5.01,-154.98 5.01,-134.98 ; 65.01,-164.98 5.01,-144.98 ; 65.01,-124.98 5.01,-144.98 ; 2849.1,-144.98 5.01,-144.98 ; 3410.93,-144.98 6255.02,-144.98 ; 6195.02,-164.98 6255.02,-144.98 ; 6195.02,-124.98 6255.02,-144.98 ; 6250,0 6450,0 ; 6250,2150 6450,2150 ; 6255.02,-194.98 6255.02,5.02 ; 6255.02,-154.98 6255.02,-134.98 ; 6385.02,65.02 6405.02,5.02 ; 6385.02,2095.01 6405.02,2155.01 ; 6395.02,5.02 6415.02,5.02 ; 6395.02,2155.01 6415.02,2155.01 ; 6405.02,804.1 6405.02,5.02 ; 6405.02,1355.93 6405.02,2155.01 ; 6425.02,65.02 6405.02,5.02 ; 6425.02,2095.01 6405.02,2155.01
  text "2150 (mil)" at 6441.01,814.1 h60 r90
  text "6250 (mil)" at 2859.1,-180.98 h60
  text ".Layer_Name" at 577,-858.49 h60
M3 3D STEP Top:
  text ".Layer_Name" at 577,-858.49 h60
M4 3D STEP Bottom:
  text ".Layer_Name" at 577,-858.49 h60
M5 Assembly Top:
  text "COMPONENTS MARKED 'DNP' SHOULD NOT BE POPULATED." at 1153.5,-318.5 h60
  text "ASSEMBLY VARIANT:" at 1153,-434 h60
  text ".VariantName" at 2189,-434 h60
  text "PCB VIEWED FROM TOP SIDE" at -228.5,-655.67 h60
  text "BOARD #:" at 2248,-655.67 h60
  text ".PRJ_Number" at 2793.5,-655.67 h60
  text "REV:" at 3638,-655.67 h60
  text ".PCB_Rev" at 3929.5,-655.67 h60
  text "SVN REV:" at 4476,-655.67 h60
  text ".VersionControl_RevNumber" at 4982,-655.67 h60
  text "TID #:" at 2248,-859 h60
  text ".TID" at 2793.5,-859 h60
  text "PLOT NAME =" at -228.5,-1064.34 h60
  text ".plot_File_Name" at 577,-1064.34 h60
  text "GENERATED    :" at 2250,-1064.34 h60
  text ".Print_Date" at 3119.5,-1064.34 h60
  text ".Print_Time" at 3848.5,-1064.34 h60
  text "TEXAS INSTRUMENTS" at 5113,-1064.34 h60
M6 Assembly Bottom:
  text "COMPONENTS MARKED 'DNP' SHOULD NOT BE POPULATED." at 6102,-318 h60
  text ".VariantName" at 5058,-434 h60
  text "ASSEMBLY VARIANT:" at 6097,-434 h60
  text ".VersionControl_RevNumber" at 1035.5,-656.17 h60
  text "SVN REV:" at 1541.5,-656.17 h60
  text ".PCB_Rev" at 2088,-656.17 h60
  text "REV:" at 2379.5,-656.17 h60
  text ".PRJ_Number" at 3224,-656.17 h60
  text "BOARD #:" at 3769.5,-656.17 h60
  text "PCB VIEWED FROM BOTTOM SIDE" at 6246,-656.17 h60
  text ".TID" at 3224,-859.5 h60
  text "TID #:" at 3769.5,-859.5 h60
  text "TEXAS INSTRUMENTS" at 904.5,-1064.84 h60
  text ".Print_Time" at 2169,-1064.84 h60
  text ".Print_Date" at 2898,-1064.84 h60
  text "GENERATED    :" at 3767.5,-1064.84 h60
  text ".plot_File_Name" at 5440.5,-1064.84 h60
  text "PLOT NAME =" at 6246,-1064.84 h60
M9 Title Sheet:
  drawing of 18 lines, arcs and shapes, not listed
  text "1" at 739.84,8036.5 h70
  text "2" at 3235.5,8036.5 h70
  text "3" at 5724.84,8036.5 h70
  text "4" at 8231.51,8036.5 h70
  text "5" at 10730.5,8036.5 h70
  text "6" at 13235.5,8036.5 h70
  text "A" at -416.5,6893.5 h70
  text "A" at 14383.5,6893.5 h70
  text "B" at -416.5,4513.5 h70
  text "B" at 14383.5,4513.5 h70
  text "C" at -416.5,2138.5 h70
  text "C" at 14383.5,2138.5 h70
  text "PROJECT TITLE:" at 11343.5,277.5 h45
  text ".PRJ_Title" at 11393.5,144.17 h70
  text "DESIGNED FOR:" at 11343.5,-23.5 h45
  text ".PRJ_Customer" at 11393.5,-163.5 h70
  text "D" at -416.5,-231.5 h70
  text "D" at 14383.5,-231.5 h70
  text "FILE NAME:" at 11343.5,-323.5 h45
  text ".PCB_File_Name_No_Path" at 11393.5,-443.5 h70
  text "Texas Instruments (TI) and/or its licensors do not warrant the accuracy or completeness of this specification" at 6374,-605.34 h45
  text "ENGINEER:" at 11343.5,-613.5 h45
  text "LAYOUT BY:" at 12848.5,-613.5 h45
  text "or any information contained therein. TI and/or its licensors do not warrant that this design will meet" at 6329.01,-718 h45
  text ".PRJ_Engineer" at 11393.5,-768.49 h70
  text ".PCB_Layout" at 12899,-768.49 h70
  text "the specifications, will be suitable for your application or fit for any particular purpose, or will operate in" at 6329.01,-830.67 h45
  text ".Layer_Name" at 577,-858.49 h60
  text "ALTIUM DESIGNER VERSION:" at 12848.5,-923.5 h45
  text "an implementation. TI and/or its licensors do not warrant that the design is production worthy. You should" at 6329.01,-943.33 h45
  text "completely validate and test your design implementation to confirm the system functionality for your application." at 6374,-1056 h45
  text ".print_Scale" at 11393.5,-1056.83 h70
  text ".Application_BuildNumber" at 12899,-1056.83 h70
  text "1" at 739.84,-1263.5 h70
  text "2" at 3235.5,-1263.5 h70
  text "3" at 5724.84,-1263.5 h70
  text "4" at 8231.51,-1263.5 h70
  text "5" at 10730.5,-1263.5 h70
  text "6" at 13235.5,-1263.5 h70
M10 Fab Notes:
  text "DESIGN INFORMATION" at 12381.02,5910 h60
  text "MIN. TRACK WIDTH:" at 11736.46,5730 h60
  text "8" at 12832.7,5730 h60
  text "MIL" at 12987.46,5730 h60
  text "MIN. CLEARANCE:" at 11736.46,5598 h60
  text "0.2" at 12772.7,5598 h60
  text "mm" at 12987.46,5598 h60
  text "MIN. VIA PAD SIZE:" at 11736.46,5466 h60
  text "24" at 12802.71,5466 h60
  text "MIL" at 12987.46,5466 h60
  text "0.05mm (2MIL)" at 12431.46,5324.29 h60
  text "MINIMUM ANNULAR RING" at 11407.23,5320 h60
  text "EXTERNAL" at 13139.46,5320 h60
  text "PER" at 11607.23,5202 h60
  text "IPC-D-275 CLASS 2 LEVEL C" at 11827.23,5202 h60
  text "MIL, HOLES" at 13315.46,5089.71 h60
  text "+/-" at 12923,5089 h60
  text "+/-" at 13777,5089 h60
  text "REGISTRATION TOLERANCES:" at 11407.23,5084 h60
  text "METAL" at 12607,5084 h60
  text "5" at 13183.2,5084 h60
  text "3" at 14016.2,5084 h60
  text "MIL" at 14132.46,5084 h60
  text "MATERIAL:" at 11332.46,4874.54 h60
  text "FR-4 High Tg" at 12318.9,4734.21 h60
  text "FR-408" at 11753.46,4725.64 h60
  text "X" at 12165.46,4725.64 h60
  text "OTHER" at 13241.46,4725.64 h60
  text "62 MIL (1.6mm) +/-10%" at 12073.56,4562.92 h60
  text "THICKNESS:" at 11407.23,4558.64 h60
  text "X" at 11945.4,4558.64 h60
  text "OTHER" at 13358.46,4558.64 h60
  text "TOLERANCE:" at 11407.23,4400.64 h60
  text "X" at 12246.53,4400.64 h60
  text "ANSI IPC-6012 TYPE 3 CLASS 2" at 12433.48,4400.64 h60
  text "OTHER +/-" at 12433.46,4244.64 h60
  text "BOW & TWIST:" at 11407.23,4087.64 h60
  text "X" at 12246.53,4087.64 h60
  text "ANSI IPC-6012 TYPE 3 CLASS 2" at 12433.48,4087.64 h60
  text "OTHER +/-" at 12433.46,3929.13 h60
  text "DRILLING:" at 11332.46,3790.64 h60
  text "REFERENCE:" at 11407.23,3673.64 h60
  text "X" at 12055.46,3673.64 h60
  text "AS SHOWN" at 12242.46,3673.64 h60
  text "X" at 12956.46,3673.64 h60
  text "NC_DRILL FILES" at 13093.46,3673.64 h60
  text "PTH MIN COPPER THICKNESS:" at 11407.23,3515.64 h60
  text "X" at 12757.46,3515.64 h60
  text "1MIL" at 12894.46,3515.64 h60
  text "OTHER" at 13391.46,3515.64 h60
  text "BOARD FINISH:" at 11332.46,3356.64 h60
  text "SILKSCREEN:" at 11487.68,3238.64 h60
  text "X" at 12436.46,3238.64 h60
  text "TOP" at 12562.46,3238.64 h60
  text "X" at 12946.46,3238.64 h60
  text "BOTTOM" at 13073.46,3238.64 h60
  text "SILKSCREEN COLOR:" at 11487.68,3071.64 h60
  text "X" at 12435.42,3071.64 h60
  text "WHITE" at 12562.46,3071.64 h60
  text "OTHER" at 13073.46,3071.64 h60
  text "SOLDER RESIST COLOR:" at 11487.68,2901.64 h60
  text "X" at 12055.42,2742.44 h60
  text "GREEN" at 12182.46,2742.44 h60
  text "BLUE" at 12773.46,2742.44 h60
  text "OTHER" at 13311.46,2742.44 h60
  text "IMMERSION GOLD (ENIG)" at 12393.46,2553.92 h60
  text "ENEPIG" at 13731,2550.64 h60
  text "SURFACE FINISH:" at 11332.46,2549.64 h60
  text "X" at 12206.51,2549.64 h60
  text "IMM. TIN/SILVER OR EQUIV" at 11662,2392.64 h60
  text "OTHER" at 13093.46,2392.64 h60
  text "ARRAY/PANEL:" at 11332.46,2213.64 h60
  text "CUT AND TRIM PER MECH LAYER 1" at 12393.46,2209.35 h60
  text "N.C. ROUTE" at 12393.46,2057.64 h60
  text "X" at 13072.46,2057.64 h60
  text "V. SCORE" at 13259.46,2057.64 h60
  text "CERTIFICATION:" at 11332.46,1920.64 h60
  text "MATERIALS AND WORKMANSHIP FOR ALL PCBS" at 12057.46,1920.64 h60
  text "TO MEET OR EXCEED THE REQUIREMENTS OF:" at 12057.46,1822.64 h60
  text "X" at 11683.96,1686.13 h60
  text "ANSI IPC-A-600F CLASS ->" at 11822.96,1686.13 h60
  text "X" at 13462.02,1686.13 h60
  text "2" at 13580.96,1686.14 h60
  text "1" at 13265.96,1684.64 h60
  text "3" at 13934.96,1684.64 h60
  text "X" at 11686.02,1526.64 h60
  text "UL 94V-0" at 11822.96,1526.64 h60
  text "X" at 12498.02,1526.64 h60
  text "RoHS" at 12634.96,1526.64 h60
  text "OTHER" at 13279.36,1526.64 h60
  text "PER ORDER" at 13676.42,1526.64 h60
  text "ADDITIONAL REQUIREMENTS:" at 11332.46,1385.64 h60
  text "MICROSECTION:" at 11407.23,1270.64 h60
  text "YES" at 12312.96,1270.64 h60
  text "REQUIRED" at 13174.46,1114.49 h60
  text "BARE BOARD ELEC. TEST:" at 11407.23,1111.64 h60
  text "NONE" at 12712.96,1111.64 h60
  text "X" at 13047.46,1111.64 h60
  text "PER ORDER" at 13766.46,1111.64 h60
  text "MANUFACTURER'S UL:" at 11407.23,954.64 h60
  text "RAIL" at 12572.96,950.35 h60
  text "METAL" at 13064.77,950.35 h60
  text "X" at 13440,950 h60
  text "SILK" at 13576.46,950.35 h60
  text ".Layer_Name" at 577,-858.49 h60
M11 Gerber Information:
  text "ALL ARTWORK VIEWED FROM TOP SIDE" at -228.5,-655.67 h60
  text "BOARD #:" at 2248,-655.67 h60
  text ".PRJ_Number" at 2793.5,-655.67 h60
  text "REV:" at 3638,-655.67 h60
  text ".PCB_Rev" at 3929.5,-655.67 h60
  text "SVN REV:" at 4476,-655.67 h60
  text ".VersionControl_RevNumber" at 4982,-655.67 h60
  text "LAYER NAME =" at -228.5,-858.49 h60
  text "TID #:" at 2248,-859 h60
  text ".TID" at 2793.5,-859 h60
  text "PLOT NAME =" at -228.5,-1064.34 h60
  text ".plot_File_Name" at 577,-1064.34 h60
  text "GENERATED    :" at 2250,-1064.34 h60
  text ".Print_Date" at 3119.5,-1064.34 h60
  text ".Print_Time" at 3848.5,-1064.34 h60
  text "TEXAS INSTRUMENTS" at 5113,-1064.34 h60
M12 Stackup:
  text ".Layer_Name" at 577,-858.49 h60
M13 Component Bodies Top:
  text ".Layer_Name" at 577,-858.49 h60
M14 Component Bodies Bottom:
  text ".Layer_Name" at 577,-858.49 h60
M15 Courtyards Top:
  text ".Layer_Name" at 577,-858.49 h60
M16 Courtyards Bottom:
  text ".Layer_Name" at 577,-858.49 h60
Drill Drawing:
  lines w10: 4086.76,3365.49 4097.83,3365.49 4097.83,3354.42 4119.97,3354.42 4119.97,3365.49 4131.04,3365.49 4131.04,3387.63 4119.97,3387.63 4119.97,3398.69 4097.83,3398.69 4097.83,3387.63 4086.76,3387.63 4086.76,3365.49 ; 4086.76,3597.94 4131.04,3597.94 4108.9,3553.66 4086.76,3597.94 ; 4086.76,3653.29 4131.04,3653.29 4131.04,3697.56 4086.76,3697.56 4086.76,3653.29 ; 4086.76,3852.53 4086.76,3863.6 4097.83,3874.67 4086.76,3885.74 4086.76,3896.81 4097.83,3896.81 4108.9,3885.74 4119.97,3896.81 4131.04,3896.81 4131.04,3885.74 4119.97,3874.67 4131.04,3863.6 4131.04,3852.53 4119.97,3852.53 4108.9,3863.6 4097.83,3852.53 4086.76,3852.53 ; 4086.76,4251.02 4108.9,4262.09 4131.04,4251.02 4119.97,4273.16 4131.04,4295.3 4108.9,4284.23 4086.76,4295.3 4097.83,4273.16 4086.76,4251.02 ; 4095.62,3369.91 4102.26,3369.91 4102.26,3363.27 4115.54,3363.27 4115.54,3369.91 4122.18,3369.91 4122.18,3383.2 4115.54,3383.2 4115.54,3389.84 4102.26,3389.84 4102.26,3383.2 4095.62,3383.2 4095.62,3369.91 ; 4095.62,3589.08 4122.18,3589.08 4108.9,3562.52 4095.62,3589.08 ; 4095.62,3662.14 4122.18,3662.14 4122.18,3688.71 4095.62,3688.71 4095.62,3662.14 ; 4095.62,3861.39 4095.62,3868.03 4102.26,3874.67 4095.62,3881.31 4095.62,3887.95 4102.26,3887.95 4108.9,3881.31 4115.54,3887.95 4122.18,3887.95 4122.18,3881.31 4115.54,3874.67 4122.18,3868.03 4122.18,3861.39 4115.54,3861.39 4108.9,3868.03 4102.26,3861.39 4095.62,3861.39 ; 4095.62,4259.87 4108.9,4266.52 4122.18,4259.87 4115.54,4273.16 4122.18,4286.44 4108.9,4279.8 4095.62,4286.44 4102.26,4273.16 4095.62,4259.87
  lines w12: 4046,3324.53 5935.11,3324.53 ; 4046,4420.38 5935.11,4420.38 ; 4361.63,3224.91 4361.63,4520 ; 4678.82,3224.91 4678.82,4520 ; 5300.56,3224.91 5300.56,4520 ; 5544.88,3224.91 5544.88,4520 ; 4046,3224.91 5935.11,3224.91 5935.11,4520 4046,4520 4046,3224.91
  text "Symbol" at 4105.77,4450.26 h72
  text "Quantity" at 4391.52,4450.26 h72
  text "Finished Hole Size" at 4708.7,4450.26 h72
  text "Plated" at 5330.45,4450.26 h72
  text "Hole Type" at 5574.77,4450.26 h72
  text "2" at 4391.52,4350.64 h60
  text "29.53mil (0.750mm)" at 4708.7,4350.64 h60
  text "NPTH" at 5330.45,4350.64 h60
  text "Round" at 5574.77,4350.64 h60
  text "B" at 4084.14,4340.65 h44.28
  text "8" at 4391.52,4251.02 h60
  text "55.91mil (1.420mm)" at 4708.7,4251.02 h60
  text "NPTH" at 5330.45,4251.02 h60
  text "Round" at 5574.77,4251.02 h60
  text "36" at 4391.52,4151.4 h60
  text "7.87mil (0.200mm)" at 4708.7,4151.4 h60
  text "PTH" at 5330.45,4151.4 h60
  text "Round" at 5574.77,4151.4 h60
  text "E" at 4084.14,4141.4 h44.28
  text "4" at 4391.52,4051.77 h60
  text "10.00mil (0.254mm)" at 4708.7,4051.77 h60
  text "PTH" at 5330.45,4051.77 h60
  text "Round" at 5574.77,4051.77 h60
  text "F" at 4084.14,4041.78 h44.28
  text "337" at 4391.52,3952.15 h60
  text "16.00mil (0.406mm)" at 4708.7,3952.15 h60
  text "PTH" at 5330.45,3952.15 h60
  text "Round" at 5574.77,3952.15 h60
  text "D" at 4084.14,3942.16 h44.28
  text "28" at 4391.52,3852.53 h60
  text "19.69mil (0.500mm)" at 4708.7,3852.53 h60
  text "PTH" at 5330.45,3852.53 h60
  text "Round" at 5574.77,3852.53 h60
  text "4" at 4391.52,3752.91 h60
  text "29.53mil (0.750mm)" at 4708.7,3752.91 h60
  text "PTH" at 5330.45,3752.91 h60
  text "Round" at 5574.77,3752.91 h60
  text "A" at 4084.14,3742.91 h44.28
  text "13" at 4391.52,3653.29 h60
  text "37.99mil (0.965mm)" at 4708.7,3653.29 h60
  text "PTH" at 5330.45,3653.29 h60
  text "Round" at 5574.77,3653.29 h60
  text "92" at 4391.52,3553.66 h60
  text "40.16mil (1.020mm)" at 4708.7,3553.66 h60
  text "PTH" at 5330.45,3553.66 h60
  text "Round" at 5574.77,3553.66 h60
  text "10" at 4391.52,3454.04 h60
  text "47.24mil (1.200mm)" at 4708.7,3454.04 h60
  text "PTH" at 5330.45,3454.04 h60
  text "Round" at 5574.77,3454.04 h60
  text "C" at 4084.14,3444.05 h44.28
  text "4" at 4391.52,3354.42 h60
  text "137.80mil (3.500mm)" at 4708.7,3354.42 h60
  text "PTH" at 5330.45,3354.42 h60
  text "Round" at 5574.77,3354.42 h60
  text "538 Total" at 4391.52,3254.8 h60
  text ".Layer_Name" at 577,-858.49 h60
